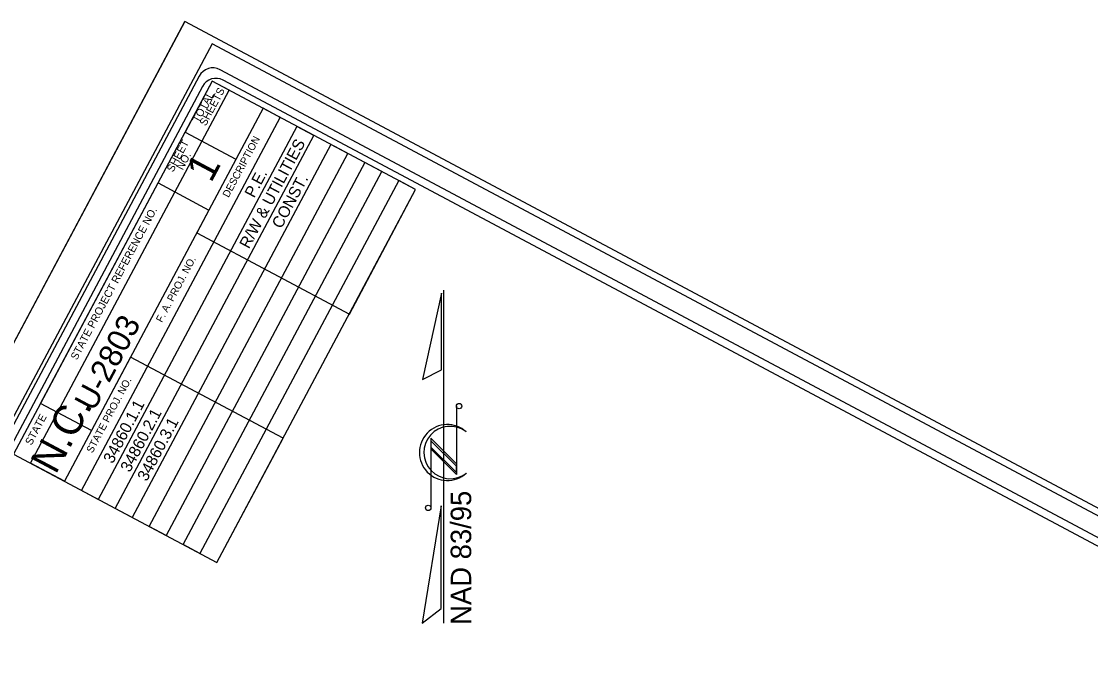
# Model space of a CAD drawing. Extents: x 1970823 to 1988115, y 770601 to 786368.
# Drawn here: x 1974936 to 1979112, y 783896 to 786368 of the extents above; entities that cross this region are included whole.
import ezdxf

# ---------------------------------------------------------------- set-up
doc = ezdxf.new("R2010")
doc.units = 0
for name, color, linetype in [('Old_Level_1', 7, 'Continuous'), ('Old_Level_11', 7, 'Continuous'), ('Old_Level_50', 7, 'Continuous'), ('Old_Level_51', 7, 'Continuous'), ('Sheet Cutting Line CELL', 7, 'Continuous'), ('Sheet Data Field CELL', 7, 'Continuous'), ('Sheet Plot Border Inside CELL', 7, 'Continuous'), ('Sheet Plot Border Outside CELL', 7, 'Continuous'), ('Sheet Title CELL', 7, 'Continuous')]:
    doc.layers.add(name, color=color, linetype=linetype)

msp = doc.modelspace()

# ---------------------------------------------------------------- linework, layer by layer
at = {"layer": 'Old_Level_1'}
for p, q in [((1976585.7, 784018.2), (1976585.7, 785318.2)), ((1976634.7, 784865.8), (1976634.7, 784599)), ((1976634.7, 784640.6), (1976535.3, 784740)), ((1976535.3, 784740), (1976535.3, 784468.8)), ((1976671.5, 784766.4), (1976672.9, 784765.4)), ((1976634.7, 784630.8), (1976535.3, 784730.2)), ((1976535.3, 784730.2), (1976535.3, 784705.8)), ((1976634.7, 784606.4), (1976535.3, 784705.8)), ((1976535.3, 784705.8), (1976634.7, 784606.4)), ((1976634.7, 784599), (1976535.3, 784698.4)), ((1976634.7, 784606.4), (1976634.7, 784630.8))]:
    msp.add_line(p, q, dxfattribs=at)
for points in [[(1976576.7, 785306.8), (1976502.5, 784969.2), (1976576.7, 785006.8)], [(1976575.1, 784476.2), (1976501.5, 784018.2), (1976575.1, 784076.2)]]:
    msp.add_lwpolyline(points, close=True, dxfattribs=at)
for centre in [(1976645.3, 784865.6), (1976524.7, 784468.4)]:
    msp.add_circle(centre, 10.6, dxfattribs=at)
for centre, radius, start, end in [((1976599.6, 784684.5), 109.2, 47.84, 312.3941), ((1976610.1, 784684.5), 102.4, 53.095, 308.6287)]:
    msp.add_arc(centre, radius, start, end, dxfattribs=at)
at = {"layer": 'Old_Level_50'}
msp.add_lwpolyline([(1975680.9, 786280.6), (1970978.5, 777456.3), (1976565.4, 774479.1), (1981267.8, 783303.4)], close=True, dxfattribs=at)
at = {"layer": 'Old_Level_51'}
msp.add_lwpolyline([(1975574.8, 786367.7), (1970823, 777450.8), (1976647.6, 774346.9), (1981399.3, 783263.8)], close=True, dxfattribs=at)
at = {"layer": 'Sheet Cutting Line CELL'}
msp.add_line((1970823, 777450.8), (1975574.8, 786367.7), dxfattribs=at)
at = {"layer": 'Sheet Plot Border Inside CELL'}
msp.add_lwpolyline([(1976565.4, 774479.1), (1981267.8, 783303.3), (1975681, 786280.5), (1970978.6, 777456.3)], close=True, dxfattribs=at)
at = {"layer": 'Sheet Plot Border Outside CELL'}
msp.add_lwpolyline([(1975574.8, 786367.7), (1970823, 777450.8), (1976647.6, 774346.9), (1981399.3, 783263.8)], close=True, dxfattribs=at)
at = {"layer": 'Sheet Title CELL'}
for points in [[(1981166, 783272.6), (1975712.2, 786178.9)], [(1975631, 786154.2), (1971454.8, 778317.4)], [(1975699.7, 784254.7), (1976475.7, 785710.9), (1976409.6, 785746.1), (1975633.5, 784290), (1975567.4, 784325.2), (1976343.4, 785781.4), (1976277.2, 785816.6), (1975501.2, 784360.6), (1975435, 784395.8), (1976210.9, 785851.9), (1976144.7, 785887.2), (1975368.8, 784431.1), (1975302.6, 784466.3), (1976078.6, 785922.5), (1976012.4, 785957.7), (1975236.5, 784501.6), (1975170.3, 784536.8), (1975946.2, 785993), (1975880, 786028.3), (1975104, 784572.2), (1974971.6, 784642.7), (1975747.6, 786098.8), (1975681.4, 786134.1), (1974905.5, 784677.9), (1975699.7, 784254.7), (1975958.4, 784740), (1975362.7, 785057.4), (1975209.9, 784770.7), (1975011.3, 784876.5), (1975469.9, 785737), (1975668.4, 785631.2), (1975621.2, 785542.7), (1976216.9, 785225.3), (1976475.7, 785710.9), (1975681.4, 786134.1), (1975575.6, 785935.6), (1975774.2, 785829.8)], [(1980145.9, 783782.2), (1975724.5, 786138.4)], [(1975643.4, 786113.6), (1971636.6, 778594.6)]]:
    msp.add_lwpolyline(points, dxfattribs=at)
for centre in [(1975683.7, 786126.1), (1975696, 786085.6)]:
    msp.add_arc(centre, 60, 61.9471, 151.9471, dxfattribs=at)

# ---------------------------------------------------------------- texts
at = {"layer": 'Old_Level_11'}
msp.add_text('NAD 83/95', height=80, rotation=90, dxfattribs=at).set_placement((1976692.7, 784011.9))
at = {"layer": 'Sheet Data Field CELL'}
for s, height, p in [('R/W & UTILITIES', 45, (1975824.6, 785477.1)), ('P.E.', 45, (1975844.8, 785675.7)), ('CONST.', 45, (1975951.2, 785555.3)), ('   U-2803    ', 90, (1975171.5, 784752.2)), ('34860.1.1', 45, (1975292.7, 784638.3)), ('34860.2.1', 45, (1975359.5, 784604.3)), ('34860.3.1', 45, (1975425.7, 784569.1))]:
    msp.add_text(s, height=height, rotation=61.9471, dxfattribs=at).set_placement(p)
at = {"layer": 'Sheet Title CELL'}
for s, height, p in [('TOTAL', 30, (1975628.7, 785969.5)), ('SHEETS', 30, (1975656.1, 785957.1)), ('SHEET', 30, (1975528.5, 785776.8)), ('DESCRIPTION', 28.8, (1975745.2, 785677.6)), ('NO.', 30, (1975566.3, 785784.8)), ('1', 116.1, (1975676.8, 785734.4)), ('STATE PROJECT REFERENCE NO.', 29.999, (1975152.8, 785043.1)), ('F. A. PROJ. NO.', 28.8, (1975485.2, 785189.9)), ('STATE PROJ. NO.', 28.8, (1975213.5, 784680)), ('N.C.', 116.1, (1975069.9, 784595.5)), ('STATE', 30, (1974975.4, 784710.4))]:
    msp.add_text(s, height=height, rotation=61.9471, dxfattribs=at).set_placement(p)

doc.saveas('drawing.dxf')
